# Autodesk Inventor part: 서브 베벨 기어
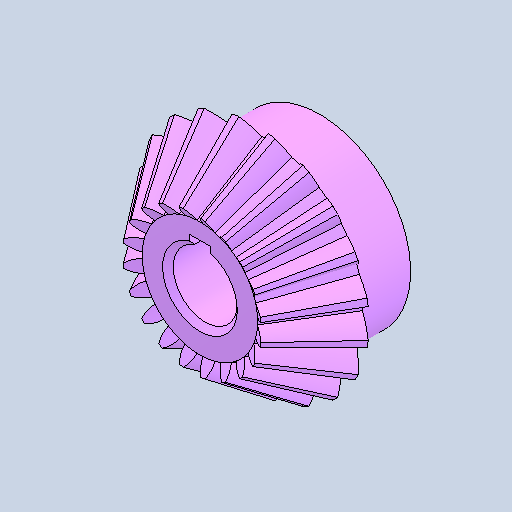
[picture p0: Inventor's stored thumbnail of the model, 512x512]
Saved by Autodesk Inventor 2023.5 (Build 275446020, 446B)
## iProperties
Created: 2026-07
Part Number: 서브 베벨 기어
Material: 강철, 합금
Document SubType Name: Modeling
Designer: mirae
Density: 7.73 g/cm^3
Appearance: 기본값
Author: jhkim
Revision Number: 1
Sending System: Autodesk Inventor 2027
Preprocessor: ST-DEVELOPER v20.1
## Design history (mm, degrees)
node "서브 베벨기어1"
  node "스케치11"
node "스케치10"
node "솔리드1"
body "Solid1"
